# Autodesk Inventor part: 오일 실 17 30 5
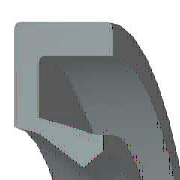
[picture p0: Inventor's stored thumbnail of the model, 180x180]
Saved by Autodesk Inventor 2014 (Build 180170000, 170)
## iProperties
Created: 2012-02
Part Number: 오일 실 17 30 5
Material: 고무
Description: 오일 실 - 스프링 장착, 비스프링, 고무 덮개 G
Document SubType Name: Modeling
Standard: JIS B 2402
Designer: mduedu
Standards Organization: JIS
Language: ko-KR
Size Designation: 17 30 5 A
Categories: <MemberInstance><Categories><Category DisplayName="샤프트 부품" InternalName="7f7aeb1f-a693-4053-b835-cee3144e0d98" Mnemonic="SHFT"><Category DisplayName="실링" Intern
Density: 0.93 g/cm^3
Appearance: 고무 - 검은색 - 버전 1.1
IsCustomPart: 1
Author: mduedu
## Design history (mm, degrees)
body "Solid1"
revolve "회전1" stored, may be unused: angle "d29" = 360 deg
chamfer "모따기1" distance "d30" = 0.25 (= 0.05 x b); stored, may be unused: second distance "d31" = 0.5 (= 0.1 x b), angle "d39" = 45 deg
chamfer "모따기2" distance "d32" = 0.5 (= 0.1 x b); stored, may be unused: second distance "d33" = 0.25 (= 0.05 x b), angle "d40" = 45 deg
fillet "모깎기1" dims "d34" = 0.25 (= 0.05 x b)
sketch "스케치2"
  geometry: L1 (9.58, -3.438)-(9.905, -5); L2 (9.147, -3.282)-(9.58, -3.438); L3 (8.5, -1.72)-(9.147, -3.282); L4 (9.682, -1.22)-(8.5, -1.72); L5 (10.811, -3.75)-(9.682, -1.22); L6 (12.111, -3.75)-(10.811, -3.75); L7 (13.556, -1.25)-(12.111, -3.75); L8 (13.556, 0)-(13.556, -1.25); L9 (15, 0)-(13.556, 0); L10 (15, -5)-(15, 0); L11 (9.905, -5)-(15, -5); L12 (0, -9.6)-(0, 1.6) reference; L13 (28, 0)-(14, 0) reference
  constraints: 22 end point, 3 horizontal, 2 vertical
  dimensions: "d2" = 5 distance of L10.start L9.start (= b); "d4" = 1.25 vertical distance of L5.start L1.end (= 0.25 x b); "d6" = 1.44444 distance of L9.start L8.start (= 0.111111 x dd - 0.111111 x Diam); "d8" = 1.25 distance of L8.start L7.start (= 0.25 x b); "d10" = 1.44444 horizontal distance of L7.start L6.start (= 0.111111 x dd - 0.111111 x Diam); "d12" = 1.21951 vertical distance of L9.start L4.start (= 0.243902 x b); "d14" = 1.18182 horizontal distance of L4.start L3.start (= 0.0909091 x dd - 0.0909091 x Diam); "d16" = 0.5 vertical distance of L4.start L3.start (= 0.1 x b); "d18" = 1.3 distance of L6.start L5.start (= 0.1 x dd - 0.1 x Diam); "d20" = 1.5625 vertical distance of L3.start L2.start (= 0.3125 x b); "d22" = 0.64677 horizontal distance of L3.start L2.start (= 0.0497512 x dd - 0.0497512 x Diam); "d24" = 0.325 horizontal distance of L1.start L1.end (= 0.025 x dd - 0.025 x Diam); "d26" = 1.5625 vertical distance of L1.start L1.end (= 0.3125 x b); "d28" = 0.43333 horizontal distance of L2.start L1.start (= 0.0333333 x dd - 0.0333333 x Diam); "d35" = 0 distance between parallel lines of L13 L9; "d36" = 15 distance between parallel lines of L12 L10 (= 0.5 x dd); "d37" = 8.5 distance from line of L12 L3.start (= 0.5 x Diam)
other parameters: "Diam" = 17 [user parameter; used in 8 equation terms], "b" = 5 [user parameter; used in 12 equation terms], "d1" = 8 (derived), "d3" = 2 (derived), "d5" = 2.22222 (derived), "d7" = 2 (derived), "d9" = 2.22222 (derived), "d11" = 1.95122 (derived), "d13" = 1.81818 (derived), "d15" = 0.8 (derived), "d17" = 2 (derived), "d19" = 2.5 (derived), "d21" = 0.99502 (derived), "d23" = 0.5 (derived), "d25" = 2.5 (derived), "d27" = 0.66667 (derived), "d38" = 0
